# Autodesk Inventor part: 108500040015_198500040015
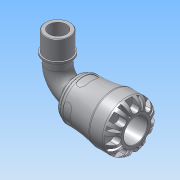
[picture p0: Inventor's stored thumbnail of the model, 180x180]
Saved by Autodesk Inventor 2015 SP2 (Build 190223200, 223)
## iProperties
Created: 2016-12
Part Number: 108500040015_198500040015
Material: PVC-Piping
Description: PLASSON 90° ELBOW WITH THREADED MALE OFFTAKE 40X1.1/2" SERIES 1
Document SubType Name: Modeling
Designer: KIM
Mass: 664.223 g
Surface Area: 733.008 cm^2
Volume: 474.445 cm^3
Density: 1.4 g/cm^3
Appearance: Smooth - White
Author: KIM
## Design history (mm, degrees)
derived "1085.ipt"
feature "Solid1::1085.ipt"
tag "TaggingFeature1"
body "Solid1"
other parameters: "d1" = 29.82, "d8" = 59.5, "d13" = 8, "d14" = 8, "d15" = 0, "d17" = 360 deg, "d19" = 8 deg, "d20" = 0.8, "d21" = 0.8, "d22" = 8 deg, "d24" = 0, "d26" = 360 deg, "d33" = 7, "d43" = 54.6, "d51" = 0.7, "d54" = 14, "d55" = 8.8, "d57" = 15.68, "d58" = 0, "d74" = 0, "d78" = 71, "d82" = 0.8, "d115" = 360 deg, "d207" = 90 deg, "d228" = 11.9, "d247" = 1.4, "d248" = 4.26, "d268" = 32.725, "d269" = 4.26, "d270" = 107, "d276" = 47.803, "d277" = 21, "d278" = 52.5833, "d280" = 23.1, "d281" = 7.17045, "d283" = 43.0227, "d286" = 0, "d287" = 0, "d288" = 33.4621, "d290" = 5.78865, "d292" = 30 deg, "l_" = 71, "A_" = 107, "l_2" = 21, "R_" = 47.803, "d9" = 10, "d289" = 33.4621
